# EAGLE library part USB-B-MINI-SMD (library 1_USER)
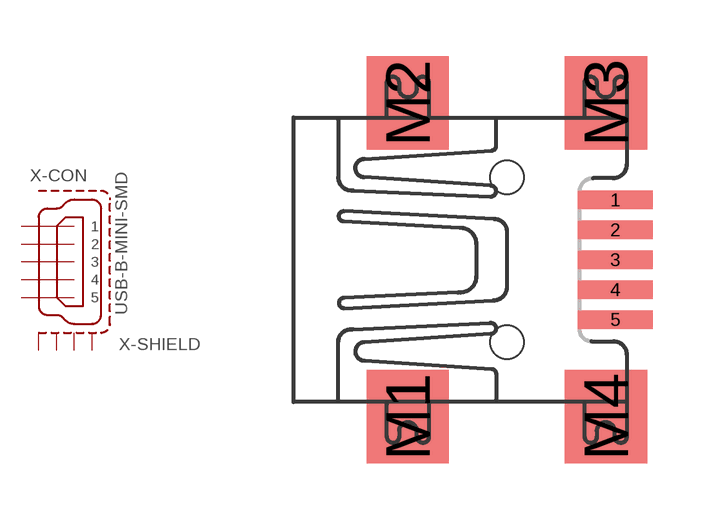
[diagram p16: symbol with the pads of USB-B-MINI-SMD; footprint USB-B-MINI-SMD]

Designator prefix X; gates -CON=USB-B-MINI -SHIELD=USB-B-MINI-SHIELD

## USB-B-MINI-SMD  [USB-B-MINI-SMD]
1  -CON:1  in
2  -CON:2  in
3  -CON:3  in
4  -CON:4  in
5  -CON:5  in
M1  -SHIELD:S1  pas
M2  -SHIELD:S2  pas
M3  -SHIELD:S3  pas
M4  -SHIELD:S4  pas

## Footprint USB-B-MINI-SMD (pad centres in mm)
smd 2 x 0.5: 1 2.9,1.6; 2 2.9,0.8; 3 2.9,0; 4 2.9,-0.8; 5 2.9,-1.6
smd 2.2 x 2.5: M1 -2.65,-4.2; M2 -2.65,4.2; M3 2.65,4.2; M4 2.65,-4.2
hole 0.9 at 0,2.2
hole 0.9 at 0,-2.2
